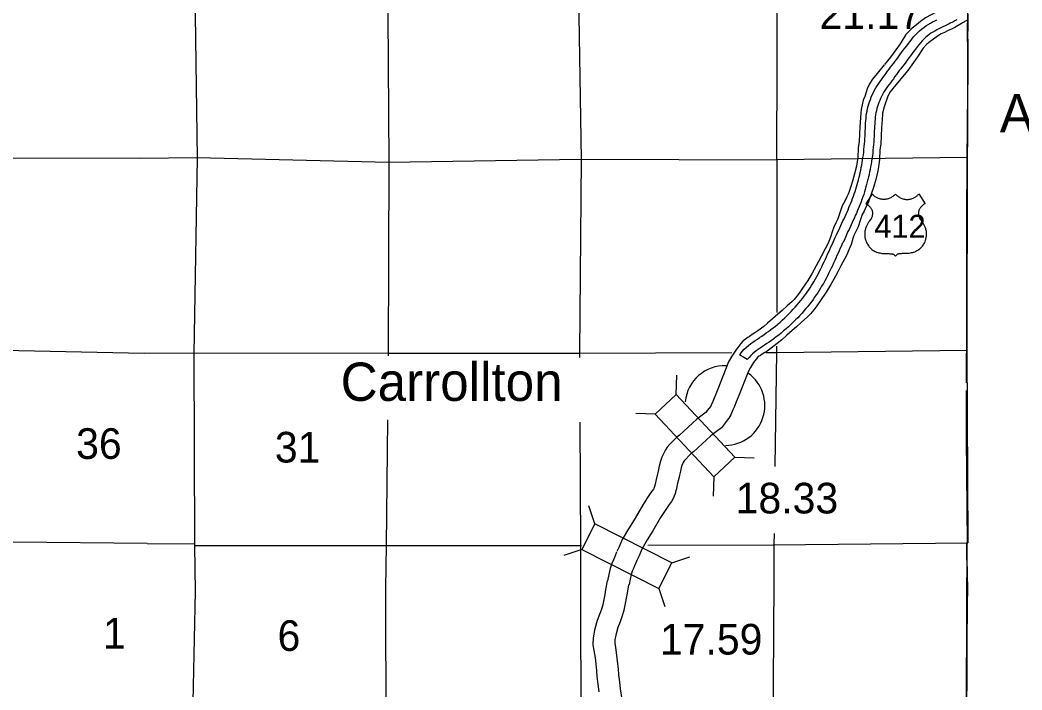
# Model space of a CAD drawing. Extents: x 77230 to 630905, y 790554 to 1662844.
# Drawn here: x 475616 to 503252, y 1547927 to 1566406 of the extents above; entities that cross this region are included whole.
import ezdxf

# ---------------------------------------------------------------- set-up
doc = ezdxf.new("R2010")
doc.units = 0
for name, color, linetype in [('Level 12', 7, 'Continuous'), ('Level 15', 7, 'Continuous'), ('Level 16', 7, 'Continuous'), ('Level 18', 7, 'Continuous'), ('Level 19', 7, 'Continuous'), ('Level 23', 7, 'Continuous'), ('Level 26', 7, 'Continuous'), ('Level 27', 7, 'Continuous'), ('Level 31', 7, 'Continuous'), ('Level 32', 7, 'Continuous'), ('Level 43', 7, 'Continuous'), ('Level 62', 7, 'Continuous')]:
    doc.layers.add(name, color=color, linetype=linetype)

msp = doc.modelspace()

# ---------------------------------------------------------------- linework, layer by layer
at = {"layer": 'Level 12'}
for points in [[(501746, 1563189), (501741, 1562613), (496495, 1562547), (496510, 1567953), (500478, 1567984)], [(501754, 1567994), (501746, 1563189)]]:
    msp.add_lwpolyline(points, dxfattribs=at)
at = {"layer": 'Level 15'}
for points in [[(480299, 1572276), (480427, 1567870), (480497, 1562600), (480409, 1557209), (480428, 1551954), (480428, 1551914), (480447, 1550642)], [(498627, 1561611), (498648, 1561675), (498669, 1561740), (498689, 1561805), (498708, 1561871), (498726, 1561937), (498744, 1562003), (498761, 1562069), (498777, 1562136), (498792, 1562202), (498806, 1562268), (498819, 1562335), (498832, 1562403), (498844, 1562473), (498855, 1562543), (498866, 1562615), (498877, 1562690), (498887, 1562764), (498895, 1562840), (498902, 1562915), (498909, 1562990), (498914, 1563064), (498919, 1563138), (498923, 1563210), (498927, 1563281), (498930, 1563352), (498934, 1563422), (498937, 1563490), (498941, 1563558), (498945, 1563626), (498951, 1563694), (498958, 1563762), (498968, 1563830), (498980, 1563897), (498995, 1563963), (499011, 1564027), (499030, 1564091), (499050, 1564154), (499072, 1564217), (499096, 1564280), (499123, 1564344), (499153, 1564409), (499187, 1564472), (499223, 1564534), (499261, 1564595), (499300, 1564655), (499341, 1564714), (499383, 1564771), (499425, 1564827), (499466, 1564883), (499507, 1564938), (499547, 1564993), (499588, 1565048), (499628, 1565102), (499670, 1565162), (499716, 1565218), (499757, 1565273), (499800, 1565331), (499844, 1565390), (499888, 1565450), (499933, 1565511), (499979, 1565573), (500026, 1565635), (500073, 1565696), (500119, 1565757), (500165, 1565817), (500212, 1565878), (500260, 1565939), (500312, 1565999), (500368, 1566056), (500424, 1566109), (500482, 1566159), (500541, 1566205), (500603, 1566249), (500665, 1566287), (500727, 1566323), (500788, 1566355), (500849, 1566385), (500908, 1566413)], [(501453, 1566411), (501400, 1566380), (501346, 1566352), (501294, 1566325), (501241, 1566298), (501186, 1566271), (501130, 1566243), (501074, 1566216), (501016, 1566188), (500959, 1566160), (500902, 1566132), (500847, 1566104), (500793, 1566073), (500741, 1566040), (500691, 1566005), (500641, 1565966), (500591, 1565923), (500543, 1565878), (500497, 1565831), (500453, 1565779), (500409, 1565724), (500363, 1565665), (500318, 1565605), (500272, 1565545), (500225, 1565484), (500179, 1565423), (500134, 1565362), (500089, 1565302), (500045, 1565241), (500001, 1565182), (499957, 1565123), (499913, 1565064), (499869, 1565011), (499831, 1564956), (499789, 1564900), (499749, 1564845), (499708, 1564789), (499667, 1564734), (499625, 1564678), (499584, 1564623), (499545, 1564569), (499507, 1564515), (499471, 1564460), (499437, 1564406), (499406, 1564351), (499377, 1564297), (499351, 1564243), (499328, 1564187), (499307, 1564131), (499287, 1564075), (499269, 1564018), (499253, 1563962), (499238, 1563905), (499225, 1563848), (499215, 1563790), (499206, 1563731), (499200, 1563670), (499195, 1563608), (499191, 1563543), (499187, 1563476), (499183, 1563409), (499180, 1563340), (499176, 1563269), (499173, 1563197), (499169, 1563123), (499164, 1563047), (499158, 1562970), (499151, 1562892), (499143, 1562813), (499135, 1562735), (499125, 1562656), (499114, 1562579), (499103, 1562505), (499091, 1562431), (499078, 1562358), (499065, 1562288), (499051, 1562218), (499036, 1562148), (499020, 1562079), (499003, 1562009), (498986, 1561940), (498967, 1561871), (498949, 1561803), (498929, 1561735), (498908, 1561666), (498886, 1561597), (498863, 1561529)], [(495673, 1557038), (495629, 1557070), (495571, 1557108), (495508, 1557147), (495463, 1557172), (495484, 1557201), (495536, 1557265), (495591, 1557325), (495650, 1557381), (495710, 1557433), (495771, 1557480), (495832, 1557525), (495893, 1557566), (495954, 1557607), (496014, 1557648), (496076, 1557689), (496138, 1557732), (496200, 1557775), (496262, 1557819), (496325, 1557866), (496388, 1557915), (496451, 1557966), (496516, 1558019), (496581, 1558076), (496645, 1558133), (496708, 1558192), (496770, 1558251), (496830, 1558310), (496889, 1558370), (496945, 1558429), (496999, 1558488), (497051, 1558548), (497102, 1558607), (497151, 1558666), (497198, 1558725), (497243, 1558785), (497287, 1558844), (497329, 1558903), (497370, 1558963), (497409, 1559022), (497447, 1559082), (497484, 1559142), (497511, 1559189), (497559, 1559268), (497595, 1559330), (497629, 1559393), (497662, 1559459), (497695, 1559528), (497729, 1559598), (497763, 1559669), (497797, 1559738), (497829, 1559806), (497860, 1559875), (497891, 1559944), (497922, 1560012), (497953, 1560079), (497983, 1560147), (498014, 1560214), (498043, 1560278), (498071, 1560348), (498094, 1560387), (498136, 1560479), (498166, 1560545), (498198, 1560611), (498226, 1560674), (498256, 1560739), (498286, 1560802), (498315, 1560865), (498344, 1560927), (498373, 1560988), (498400, 1561049), (498427, 1561111), (498454, 1561172), (498480, 1561234), (498506, 1561296), (498531, 1561358), (498556, 1561420), (498580, 1561483), (498604, 1561546), (498627, 1561611)], [(498863, 1561529), (498839, 1561460), (498814, 1561394), (498789, 1561329), (498763, 1561264), (498737, 1561201), (498711, 1561137), (498684, 1561074), (498656, 1561011), (498629, 1560947), (498600, 1560884), (498571, 1560821), (498542, 1560759), (498512, 1560696), (498482, 1560633), (498453, 1560570), (498424, 1560505), (498392, 1560439), (498363, 1560375), (498316, 1560273), (498297, 1560239), (498273, 1560180), (498241, 1560111), (498211, 1560044), (498181, 1559976), (498150, 1559909), (498119, 1559840), (498088, 1559771), (498056, 1559701), (498022, 1559630), (497988, 1559560), (497955, 1559490), (497920, 1559419), (497886, 1559348), (497851, 1559278), (497813, 1559208), (497774, 1559141), (497727, 1559062), (497699, 1559014), (497659, 1558949), (497619, 1558886), (497577, 1558823), (497534, 1558760), (497489, 1558697), (497443, 1558635), (497395, 1558572), (497345, 1558509), (497294, 1558446), (497240, 1558384), (497185, 1558321), (497128, 1558258), (497068, 1558196), (497007, 1558134), (496944, 1558072), (496880, 1558010), (496813, 1557948), (496746, 1557888), (496678, 1557829), (496610, 1557772), (496543, 1557718), (496476, 1557667), (496410, 1557617), (496344, 1557570), (496279, 1557525), (496216, 1557483), (496154, 1557441), (496093, 1557399), (496033, 1557359), (495976, 1557320), (495921, 1557280), (495868, 1557239), (495818, 1557196), (495770, 1557150), (495725, 1557101), (495673, 1557038)], [(479121, 1551968), (475435, 1552000), (475181, 1551997), (470150, 1552090), (469836, 1552104), (464890, 1552185), (464531, 1552192), (459599, 1552293), (459245, 1552297), (458894, 1552305)], [(479121, 1551968), (480428, 1551954)], [(480428, 1551914), (485685, 1551913), (491092, 1551914), (491102, 1551914)], [(492928, 1551921), (496394, 1551934), (501756, 1551982)], [(480447, 1550642), (480363, 1546730), (480386, 1541432), (480408, 1535936), (480643, 1532876)]]:
    msp.add_lwpolyline(points, dxfattribs=at)
at = {"layer": 'Level 16'}
for points in [[(485721, 1569687), (485750, 1567946), (485786, 1562463), (485770, 1557191), (485770, 1557142)], [(491015, 1567661), (491094, 1562570), (491044, 1557222), (491045, 1557102)], [(478938, 1562590), (475144, 1562599), (469892, 1562658), (464597, 1562760), (459288, 1562901), (454750, 1562996)], [(496495, 1562537), (491088, 1562560), (485786, 1562473), (480495, 1562604), (478938, 1562590)], [(496493, 1562537), (496487, 1558336)], [(479039, 1557211), (475151, 1557287), (469861, 1557367), (464571, 1557455), (459248, 1557573), (454860, 1557710)], [(496485, 1557413), (496485, 1557241), (496439, 1554092)], [(495246, 1557224), (491035, 1557212), (485770, 1557211), (480399, 1557213), (479039, 1557211)], [(501729, 1557288), (496492, 1557227), (496189, 1557226)], [(485752, 1555376), (485717, 1551910), (485693, 1550738)], [(491057, 1555316), (491078, 1551902), (491074, 1550827)], [(496413, 1552246), (496408, 1551939), (496407, 1550938)], [(485693, 1550738), (485702, 1546720), (485771, 1541378), (485814, 1535901), (485851, 1534680)], [(491074, 1550827), (491085, 1546699), (491079, 1544190)], [(496407, 1550938), (496385, 1546668), (496417, 1541174), (496405, 1535904), (496509, 1530581), (496569, 1525267), (496568, 1519909), (496460, 1514735), (496452, 1509537), (496466, 1504229)]]:
    msp.add_lwpolyline(points, dxfattribs=at)
at = {"layer": 'Level 18'}
for points in [[(501745, 1566321), (501751, 1565286), (501743, 1562613), (501729, 1557288), (501756, 1551982), (501722, 1551979), (501732, 1551026)], [(501745, 1566321), (501751, 1565286), (501743, 1562613), (501729, 1557288), (501756, 1551982), (501722, 1551979), (501732, 1551026)], [(501865, 1504258), (501749, 1509481), (501816, 1514734), (501843, 1519952), (501910, 1525289), (501796, 1530588), (501673, 1535885), (501658, 1541192), (501719, 1546631), (501732, 1551026)], [(501865, 1504258), (501749, 1509481), (501816, 1514734), (501843, 1519952), (501910, 1525289), (501796, 1530588), (501673, 1535885), (501658, 1541192), (501719, 1546631), (501732, 1551026)]]:
    msp.add_lwpolyline(points, dxfattribs=at)
at = {"layer": 'Level 19'}
for p, q in [((493712, 1556079), (493729, 1556606)), ((493712, 1556079), (493729, 1556606)), ((493133, 1555537), (492606, 1555555)), ((493133, 1555537), (492606, 1555555)), ((495335, 1554344), (495863, 1554326)), ((495335, 1554344), (495863, 1554326)), ((494757, 1553803), (494739, 1553275)), ((494757, 1553803), (494739, 1553275)), ((491469, 1552505), (491303, 1553006)), ((491112, 1551797), (490611, 1551632)), ((493591, 1551436), (494092, 1551601)), ((493234, 1550728), (493400, 1550227))]:
    msp.add_line(p, q, dxfattribs=at)
for points in [[(495335, 1554344), (493712, 1556079), (493133, 1555537), (494757, 1553803)], [(495335, 1554344), (493712, 1556079), (493133, 1555537), (494757, 1553803)], [(493591, 1551436), (491469, 1552505), (491112, 1551797), (493234, 1550728)]]:
    msp.add_lwpolyline(points, close=True, dxfattribs=at)
at = {"layer": 'Level 23'}
for points in [[(501628, 1567287), (501506, 1567145), (501428, 1567032), (501398, 1566943), (501373, 1566887), (501369, 1566880), (501369, 1566880), (501310, 1566842), (501240, 1566798), (501122, 1566735), (501051, 1566698), (500960, 1566658), (500850, 1566603), (500746, 1566554), (500593, 1566465), (500452, 1566364), (500341, 1566278), (500224, 1566180), (500053, 1566006), (499892, 1565752), (499772, 1565583), (499629, 1565382), (499456, 1565178)], [(501628, 1567287), (501506, 1567145), (501428, 1567032), (501398, 1566943), (501373, 1566887), (501369, 1566880), (501369, 1566880), (501310, 1566842), (501240, 1566798), (501122, 1566735), (501051, 1566698), (500960, 1566658), (500850, 1566603), (500746, 1566554), (500593, 1566465), (500452, 1566364), (500341, 1566278), (500224, 1566180), (500053, 1566006), (499892, 1565752), (499772, 1565583), (499629, 1565382), (499456, 1565178)], [(501729, 1566400), (501713, 1566388), (501633, 1566337), (501543, 1566280), (501402, 1566204), (501310, 1566156), (501214, 1566114), (501112, 1566063), (501025, 1566022), (500919, 1565960), (500810, 1565883), (500718, 1565811), (500632, 1565739), (500526, 1565631), (500390, 1565417), (500261, 1565236), (500103, 1565013), (499912, 1564789)], [(501729, 1566400), (501713, 1566388), (501633, 1566337), (501543, 1566280), (501402, 1566204), (501310, 1566156), (501214, 1566114), (501112, 1566063), (501025, 1566022), (500919, 1565960), (500810, 1565883), (500718, 1565811), (500632, 1565739), (500526, 1565631), (500390, 1565417), (500261, 1565236), (500103, 1565013), (499912, 1564789)], [(499452, 1565175), (499256, 1564936), (499130, 1564772), (499050, 1564649), (498985, 1564505), (498953, 1564414), (498916, 1564298), (498875, 1564197), (498814, 1563938), (498806, 1563849), (498788, 1563576), (498781, 1563463), (498761, 1563057), (498732, 1562880), (498722, 1562609), (498710, 1562502), (498686, 1562371), (498636, 1562162), (498580, 1561959), (498533, 1561815), (498486, 1561674), (498460, 1561607), (498421, 1561529), (498365, 1561412), (498294, 1561284), (498227, 1561088), (498175, 1560927), (498120, 1560815), (498063, 1560697), (498017, 1560565), (497971, 1560413), (497927, 1560301), (497881, 1560200), (497823, 1560095), (497726, 1559906), (497640, 1559745), (497576, 1559623), (497460, 1559410), (497346, 1559225), (497198, 1559009), (497108, 1558875), (497042, 1558787), (496968, 1558699), (496913, 1558640), (496776, 1558521), (496639, 1558398), (496519, 1558296), (496368, 1558161), (496236, 1558044), (496129, 1557955), (495966, 1557836), (495888, 1557774), (495840, 1557747), (495736, 1557676), (495727, 1557669), (495699, 1557654), (495587, 1557578), (495550, 1557546), (495495, 1557487), (495357, 1557303), (495246, 1557132), (495162, 1556978), (494862, 1556228), (494807, 1556089), (494765, 1555977), (494726, 1555888), (494682, 1555784), (494667, 1555757), (494620, 1555696), (494571, 1555634), (494537, 1555590), (494466, 1555537), (494286, 1555400), (493808, 1554953), (493736, 1554898), (493642, 1554811), (493538, 1554703), (493465, 1554622), (493423, 1554550), (493379, 1554476), (493319, 1554346), (493278, 1554234), (493244, 1554099), (493215, 1553961), (493203, 1553891), (493161, 1553736), (493135, 1553604), (493119, 1553542), (493115, 1553526), (493111, 1553512), (493100, 1553484), (493087, 1553462), (493017, 1553378), (492902, 1553205), (492772, 1552994), (492557, 1552623), (492403, 1552376), (492229, 1552077), (492145, 1551873), (492081, 1551745)], [(499452, 1565175), (499256, 1564936), (499130, 1564772), (499050, 1564649), (498985, 1564505), (498953, 1564414), (498916, 1564298), (498875, 1564197), (498814, 1563938), (498806, 1563849), (498788, 1563576), (498781, 1563463), (498761, 1563057), (498732, 1562880), (498722, 1562609), (498710, 1562502), (498686, 1562371), (498636, 1562162), (498580, 1561959), (498533, 1561815), (498486, 1561674), (498460, 1561607), (498421, 1561529), (498365, 1561412), (498294, 1561284), (498227, 1561088), (498175, 1560927), (498120, 1560815), (498063, 1560697), (498017, 1560565), (497971, 1560413), (497927, 1560301), (497881, 1560200), (497823, 1560095), (497726, 1559906), (497640, 1559745), (497576, 1559623), (497460, 1559410), (497346, 1559225), (497198, 1559009), (497108, 1558875), (497042, 1558787), (496968, 1558699), (496913, 1558640), (496776, 1558521), (496639, 1558398), (496519, 1558296), (496368, 1558161), (496236, 1558044), (496129, 1557955), (495966, 1557836), (495888, 1557774), (495840, 1557747), (495736, 1557676), (495727, 1557669), (495699, 1557654), (495587, 1557578), (495550, 1557546), (495495, 1557487), (495357, 1557303), (495246, 1557132), (495162, 1556978), (494862, 1556228), (494807, 1556089), (494765, 1555977), (494726, 1555888), (494682, 1555784), (494667, 1555757), (494620, 1555696), (494571, 1555634), (494537, 1555590), (494466, 1555537), (494286, 1555400), (493808, 1554953), (493736, 1554898), (493642, 1554811), (493538, 1554703), (493465, 1554622), (493423, 1554550), (493379, 1554476), (493319, 1554346), (493278, 1554234), (493244, 1554099), (493215, 1553961), (493203, 1553891), (493161, 1553736), (493135, 1553604), (493119, 1553542), (493115, 1553526), (493111, 1553512), (493100, 1553484), (493087, 1553462), (493017, 1553378), (492902, 1553205), (492772, 1552994), (492557, 1552623), (492403, 1552376), (492229, 1552077), (492145, 1551873), (492081, 1551745)], [(499916, 1564793), (499725, 1564562), (499620, 1564425), (499578, 1564360), (499542, 1564281), (499522, 1564226), (499482, 1564095), (499449, 1564013), (499407, 1563840), (499404, 1563801), (499386, 1563539), (499380, 1563431), (499358, 1562994), (499330, 1562820), (499321, 1562565), (499304, 1562415), (499273, 1562247), (499217, 1562012), (499155, 1561787), (499103, 1561627), (499051, 1561472), (499010, 1561365), (498959, 1561264), (498898, 1561137), (498844, 1561040), (498797, 1560900), (498733, 1560701), (498660, 1560552), (498618, 1560467), (498588, 1560379), (498539, 1560216), (498479, 1560065), (498417, 1559929), (498353, 1559814), (498258, 1559628), (498170, 1559464), (498105, 1559340), (497979, 1559109), (497849, 1558898), (497695, 1558672), (497597, 1558527), (497513, 1558414), (497417, 1558300), (497329, 1558207), (497173, 1558072), (497034, 1557946), (496912, 1557844), (496767, 1557713), (496627, 1557589), (496499, 1557482), (496330, 1557359), (496223, 1557274), (496157, 1557237), (496085, 1557187), (496044, 1557157), (496005, 1557137), (495962, 1557108), (495955, 1557101), (495850, 1556960), (495762, 1556824), (495706, 1556721), (495420, 1556006), (495367, 1555873), (495320, 1555750), (495277, 1555651), (495220, 1555516), (495167, 1555424), (495095, 1555329), (495043, 1555264), (494962, 1555160), (494829, 1555059), (494673, 1554941), (494194, 1554492), (494122, 1554438), (494064, 1554384), (493978, 1554294), (493950, 1554264), (493939, 1554245), (493911, 1554197), (493873, 1554116), (493852, 1554057), (493829, 1553966), (493805, 1553850), (493790, 1553762), (493746, 1553598), (493720, 1553472), (493700, 1553392), (493694, 1553368), (493680, 1553317), (493643, 1553227), (493587, 1553124), (493499, 1553018), (493407, 1552880), (493286, 1552686), (493071, 1552314), (492917, 1552066), (492768, 1551811), (492691, 1551624), (492616, 1551475)], [(499916, 1564793), (499725, 1564562), (499620, 1564425), (499578, 1564360), (499542, 1564281), (499522, 1564226), (499482, 1564095), (499449, 1564013), (499407, 1563840), (499404, 1563801), (499386, 1563539), (499380, 1563431), (499358, 1562994), (499330, 1562820), (499321, 1562565), (499304, 1562415), (499273, 1562247), (499217, 1562012), (499155, 1561787), (499103, 1561627), (499051, 1561472), (499010, 1561365), (498959, 1561264), (498898, 1561137), (498844, 1561040), (498797, 1560900), (498733, 1560701), (498660, 1560552), (498618, 1560467), (498588, 1560379), (498539, 1560216), (498479, 1560065), (498417, 1559929), (498353, 1559814), (498258, 1559628), (498170, 1559464), (498105, 1559340), (497979, 1559109), (497849, 1558898), (497695, 1558672), (497597, 1558527), (497513, 1558414), (497417, 1558300), (497329, 1558207), (497173, 1558072), (497034, 1557946), (496912, 1557844), (496767, 1557713), (496627, 1557589), (496499, 1557482), (496330, 1557359), (496223, 1557274), (496157, 1557237), (496085, 1557187), (496044, 1557157), (496005, 1557137), (495962, 1557108), (495955, 1557101), (495850, 1556960), (495762, 1556824), (495706, 1556721), (495420, 1556006), (495367, 1555873), (495320, 1555750), (495277, 1555651), (495220, 1555516), (495167, 1555424), (495095, 1555329), (495043, 1555264), (494962, 1555160), (494829, 1555059), (494673, 1554941), (494194, 1554492), (494122, 1554438), (494064, 1554384), (493978, 1554294), (493950, 1554264), (493939, 1554245), (493911, 1554197), (493873, 1554116), (493852, 1554057), (493829, 1553966), (493805, 1553850), (493790, 1553762), (493746, 1553598), (493720, 1553472), (493700, 1553392), (493694, 1553368), (493680, 1553317), (493643, 1553227), (493587, 1553124), (493499, 1553018), (493407, 1552880), (493286, 1552686), (493071, 1552314), (492917, 1552066), (492768, 1551811), (492691, 1551624), (492616, 1551475)], [(492071, 1551725), (492013, 1551583), (491983, 1551516), (491940, 1551415), (491897, 1551280), (491854, 1551115), (491822, 1550936)], [(492071, 1551725), (492013, 1551583), (491983, 1551516), (491940, 1551415), (491897, 1551280), (491854, 1551115), (491822, 1550936)], [(492626, 1551496), (492565, 1551349), (492535, 1551279), (492503, 1551205), (492474, 1551113), (492441, 1550987), (492414, 1550834), (492412, 1550823)], [(492626, 1551496), (492565, 1551349), (492535, 1551279), (492503, 1551205), (492474, 1551113), (492441, 1550987), (492414, 1550834), (492412, 1550823)], [(491587, 1547879), (491560, 1548084), (491539, 1548295), (491528, 1548450), (491504, 1548647), (491485, 1548809), (491454, 1549011), (491429, 1549174), (491431, 1549366), (491480, 1549625), (491547, 1549855), (491612, 1550018), (491662, 1550167), (491699, 1550284), (491729, 1550424), (491753, 1550564), (491777, 1550702), (491822, 1550936)], [(492223, 1547662), (492182, 1547959), (492156, 1548153), (492137, 1548346), (492125, 1548507), (492100, 1548717), (492080, 1548890), (492047, 1549102), (492030, 1549215), (492031, 1549307), (492064, 1549484), (492115, 1549659), (492176, 1549813), (492232, 1549983), (492279, 1550129), (492318, 1550309), (492344, 1550462), (492368, 1550594), (492412, 1550823)]]:
    msp.add_lwpolyline(points, dxfattribs=at)
at = {"layer": 'Level 26'}
for start, end in [(88.1858, 174.5719), (270.7848, 53.8807)]:
    msp.add_arc((495060, 1555772), 1100, start, end, dxfattribs=at)
at = {"layer": 'Level 43'}
msp.add_line((501721, 1551977), (501744, 1551977), dxfattribs=at)
for points in [[(501751, 1566509), (501751, 1566478), (501762, 1565290)], [(501760, 1566571), (501762, 1566098)], [(501762, 1565353), (501762, 1565290)], [(501762, 1565290), (501736, 1562544), (501730, 1561871), (501719, 1561599), (501723, 1557283), (501712, 1557163), (501712, 1556396)], [(501762, 1565290), (501741, 1562613), (501721, 1557290), (501725, 1556614)], [(501728, 1556191), (501751, 1551986), (501728, 1551985), (501711, 1546647)], [(501712, 1556187), (501712, 1554871), (501744, 1551977)], [(501721, 1551977), (501747, 1550709), (501745, 1550313), (501733, 1549176), (501724, 1546621), (501654, 1541172), (501659, 1539970), (501664, 1538811), (501658, 1538571), (501669, 1536359), (501663, 1535885), (501784, 1531126)]]:
    msp.add_lwpolyline(points, dxfattribs=at)
at = {"layer": 'Level 62'}
for points in [[(499764, 1561607), (499751, 1561592), (499738, 1561579), (499724, 1561566), (499708, 1561553), (499693, 1561541), (499675, 1561529), (499656, 1561517), (499634, 1561504), (499606, 1561491), (499584, 1561483), (499560, 1561475), (499538, 1561469), (499517, 1561465), (499496, 1561462), (499476, 1561460), (499449, 1561459), (499427, 1561459), (499407, 1561460), (499389, 1561462), (499370, 1561465), (499347, 1561469), (499326, 1561475), (499299, 1561484), (499277, 1561492), (499257, 1561502), (499238, 1561511), (499221, 1561522), (499202, 1561534), (499184, 1561547), (499169, 1561559), (499156, 1561571), (499143, 1561583), (499131, 1561597), (499120, 1561609), (498947, 1561341), (498960, 1561334), (498974, 1561324), (498988, 1561314), (499007, 1561299), (499022, 1561287), (499035, 1561274), (499048, 1561261), (499062, 1561245), (499072, 1561234), (499082, 1561221), (499091, 1561207), (499101, 1561193), (499110, 1561176), (499117, 1561155), (499122, 1561134), (499125, 1561112), (499128, 1561092), (499128, 1561072), (499128, 1561053), (499127, 1561038), (499124, 1561020), (499121, 1561003), (499116, 1560985), (499111, 1560968), (499104, 1560950), (499092, 1560926), (499081, 1560908), (499067, 1560891), (499050, 1560869), (499036, 1560850), (499023, 1560831), (499012, 1560813), (499002, 1560796), (498993, 1560780), (498983, 1560761), (498973, 1560740), (498963, 1560718), (498957, 1560702), (498949, 1560682), (498941, 1560657), (498934, 1560636), (498928, 1560614), (498922, 1560587), (498918, 1560564), (498915, 1560540), (498914, 1560513), (498914, 1560488), (498915, 1560463), (498918, 1560435), (498922, 1560408), (498927, 1560387), (498931, 1560369), (498937, 1560348), (498945, 1560323), (498957, 1560292), (498967, 1560269), (498978, 1560246), (498991, 1560223), (499007, 1560197), (499024, 1560173), (499040, 1560152), (499058, 1560130), (499082, 1560105), (499103, 1560087), (499124, 1560069)], [(499764, 1561607), (499777, 1561592), (499789, 1561579), (499804, 1561566), (499819, 1561553), (499834, 1561541), (499852, 1561529), (499872, 1561517), (499894, 1561504), (499922, 1561491), (499943, 1561483), (499967, 1561475), (499990, 1561469), (500010, 1561465), (500032, 1561462), (500052, 1561460), (500079, 1561459), (500101, 1561459), (500120, 1561460), (500138, 1561462), (500157, 1561465), (500180, 1561469), (500202, 1561475), (500228, 1561484), (500251, 1561492), (500271, 1561502), (500289, 1561511), (500306, 1561522), (500326, 1561534), (500343, 1561547), (500358, 1561559), (500371, 1561571), (500384, 1561583), (500397, 1561597), (500407, 1561609), (500580, 1561341), (500568, 1561334), (500553, 1561324), (500539, 1561314), (500521, 1561299), (500506, 1561287), (500493, 1561274), (500479, 1561261), (500465, 1561245), (500456, 1561234), (500446, 1561221), (500436, 1561207), (500427, 1561193), (500418, 1561176), (500411, 1561155), (500406, 1561134), (500402, 1561112), (500400, 1561092), (500399, 1561072), (500400, 1561053), (500401, 1561038), (500403, 1561020), (500407, 1561003), (500412, 1560985), (500417, 1560968), (500424, 1560950), (500435, 1560926), (500447, 1560908), (500461, 1560891), (500478, 1560869), (500491, 1560850), (500504, 1560831), (500516, 1560813), (500526, 1560796), (500535, 1560780), (500544, 1560761), (500555, 1560740), (500564, 1560718), (500571, 1560702), (500578, 1560682), (500587, 1560657), (500593, 1560636), (500600, 1560614), (500606, 1560587), (500609, 1560564), (500612, 1560540), (500614, 1560513), (500614, 1560488), (500613, 1560463), (500610, 1560435), (500605, 1560408), (500601, 1560387), (500596, 1560369), (500590, 1560348), (500582, 1560323), (500571, 1560292), (500561, 1560269), (500550, 1560246), (500537, 1560223), (500521, 1560197), (500504, 1560173), (500488, 1560152), (500469, 1560130), (500445, 1560105), (500425, 1560087), (500404, 1560069)], [(499124, 1560069), (499145, 1560053), (499171, 1560036), (499204, 1560021), (499242, 1560006), (499274, 1559996), (499302, 1559988), (499334, 1559981), (499364, 1559975), (499396, 1559971), (499436, 1559968), (499467, 1559966), (499494, 1559967), (499519, 1559966), (499545, 1559966), (499570, 1559964), (499591, 1559963), (499612, 1559961), (499639, 1559958), (499665, 1559955), (499681, 1559953), (499694, 1559950), (499710, 1559944), (499719, 1559939), (499727, 1559934), (499737, 1559925), (499748, 1559914), (499756, 1559904), (499764, 1559891)], [(500404, 1560069), (500382, 1560053), (500356, 1560036), (500323, 1560021), (500285, 1560006), (500254, 1559996), (500226, 1559988), (500194, 1559981), (500164, 1559975), (500132, 1559971), (500091, 1559968), (500060, 1559966), (500034, 1559967), (500008, 1559966), (499982, 1559966), (499958, 1559964), (499937, 1559963), (499916, 1559961), (499889, 1559958), (499862, 1559955), (499847, 1559953), (499834, 1559950), (499818, 1559944), (499809, 1559939), (499801, 1559934), (499790, 1559925), (499780, 1559914), (499771, 1559904), (499764, 1559891)]]:
    msp.add_lwpolyline(points, dxfattribs=at)

# ---------------------------------------------------------------- texts
at = {"layer": 'Level 16'}
for s, height, p in [('36', 844.8, (477163, 1554301)), ('31', 844.8, (482645, 1554201)), ('1', 845, (477905, 1549070)), ('6', 845, (482719, 1549004))]:
    msp.add_text(s, height=height, dxfattribs=at).set_placement(p)
at = {"layer": 'Level 26'}
msp.add_text('Carrollton', height=1056, dxfattribs=at).set_placement((484460, 1555901))
at = {"layer": 'Level 27'}
msp.add_text('ALPENA', height=1056, dxfattribs=at).set_placement((502639, 1563306))
at = {"layer": 'Level 31'}
msp.add_text('21.17', height=844.8, dxfattribs=at).set_placement((497669, 1566159))
at = {"layer": 'Level 32'}
for s, p in [('18.33', (495356, 1552796)), ('17.59', (493266, 1548904))]:
    msp.add_text(s, height=844.8, dxfattribs=at).set_placement(p)
at = {"layer": 'Level 62'}
msp.add_text('412', height=633.6, dxfattribs=at).set_placement((499181, 1560400))

doc.saveas('drawing.dxf')
